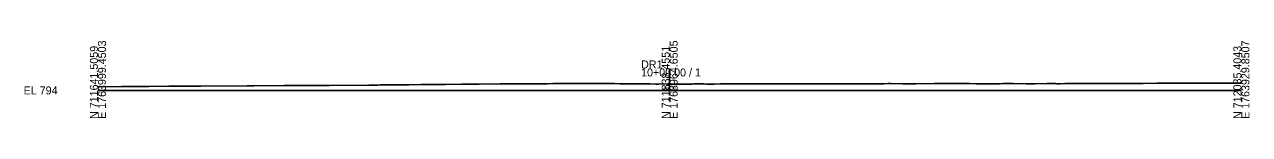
# Model space of a CAD drawing. Extents: x -26 to 403, y -10 to 2023.
# Drawn here: x -25.7 to 402.8, y -9.7 to 17.3 of the extents above; entities that cross this region are included whole.
import ezdxf

# ---------------------------------------------------------------- set-up
doc = ezdxf.new("R2010")
doc.units = 0
for name, color, linetype in [('Exist Cross Section Cell', 7, 'Continuous'), ('Exist XS Center Line Elevation Label', 7, 'Continuous'), ('Exist XS Ground Line', 7, 'Continuous')]:
    doc.layers.add(name, color=color, linetype=linetype)

msp = doc.modelspace()

# ---------------------------------------------------------------- linework, layer by layer
at = {"layer": 'Exist Cross Section Cell'}
for p, q in [((200, 0), (200, 7.69)), ((0, 0), (200, 0)), ((200, 0), (400, 0))]:
    msp.add_line(p, q, dxfattribs=at)
at = {"layer": 'Exist XS Ground Line'}
msp.add_lwpolyline([(0, 1.29), (0.57, 1.3), (8.3, 1.34), (9.9, 1.35), (11.26, 1.36), (12.43, 1.37), (14.28, 1.38), (14.97, 1.38), (16.73, 1.39), (17.82, 1.4), (24.81, 1.45), (26.57, 1.46), (27.67, 1.47), (28.43, 1.48), (31.35, 1.5), (35.98, 1.53), (52.25, 1.62), (53.93, 1.64), (54.48, 1.64), (65.05, 1.69), (66.66, 1.7), (70.69, 1.72), (71.27, 1.72), (77.56, 1.73), (79.66, 1.75), (80.09, 1.75), (80.92, 1.76), (94.82, 1.87), (97.46, 1.88), (97.86, 1.88), (98.71, 1.9), (108.77, 1.99), (112.91, 2.03), (113.98, 2.04), (115.2, 2.05), (116, 2.06), (116.52, 2.06), (119.1, 2.09), (120.82, 2.11), (121.12, 2.11), (121.57, 2.12), (127.19, 2.16), (127.57, 2.16), (128.26, 2.18), (129.22, 2.19), (131.41, 2.18), (131.75, 2.18), (133.34, 2.24), (134.5, 2.26), (136.83, 2.24), (137.58, 2.25), (139.37, 2.24), (140.67, 2.25), (141.91, 2.26), (143.75, 2.25), (144.45, 2.26), (146.99, 2.28), (147.7, 2.29), (149.52, 2.32), (149.92, 2.32), (152.06, 2.33), (153, 2.33), (154.6, 2.33), (156.08, 2.33), (157.14, 2.33), (159.17, 2.39), (159.68, 2.39), (162.25, 2.39), (164.76, 2.39), (165.33, 2.39), (167.3, 2.42), (168.42, 2.41), (169.83, 2.39), (171.5, 2.4), (172.37, 2.4), (174.58, 2.4), (174.91, 2.4), (176.44, 2.41), (177.67, 2.42), (179.99, 2.37), (180.75, 2.37), (182.53, 2.33), (183.84, 2.32), (185.07, 2.31), (186.92, 2.3), (187.61, 2.31), (190.24, 2.28), (190.81, 2.28), (192.68, 2.28), (193.09, 2.28), (195.22, 2.23), (196.17, 2.24), (197.76, 2.25), (199.25, 2.24), (200.3, 2.23), (202.34, 2.21), (202.84, 2.21), (205.42, 2.18), (207.92, 2.24), (208.5, 2.25), (210.45, 2.26), (211.82, 2.25), (212.99, 2.24), (214.67, 2.24), (215.53, 2.23), (217.75, 2.25), (218.07, 2.25), (218.81, 2.27), (219.7, 2.28), (220.03, 2.28), (220.48, 2.28), (227.05, 2.3), (227.39, 2.3), (227.95, 2.29), (229.23, 2.3), (230.09, 2.3), (230.76, 2.3), (231.24, 2.3), (232.93, 2.3), (234.64, 2.32), (235.84, 2.32), (237.01, 2.32), (237.42, 2.32), (241.01, 2.33), (241.43, 2.33), (242.16, 2.33), (243.72, 2.33), (250.46, 2.32), (254.76, 2.3), (256.15, 2.3), (257.13, 2.3), (257.84, 2.3), (258.69, 2.3), (259.92, 2.3), (260.92, 2.3), (261.78, 2.29), (262.66, 2.3), (263.07, 2.3), (270.18, 2.31), (270.53, 2.31), (271.11, 2.32), (272.35, 2.33), (273.26, 2.34), (273.92, 2.34), (274.97, 2.34), (276.46, 2.36), (277.41, 2.36), (281.6, 2.34), (282.04, 2.35), (282.71, 2.35), (283.82, 2.35), (286.05, 2.35), (292.51, 2.36), (296.87, 2.36), (297.41, 2.36), (298.23, 2.37), (299.61, 2.36), (301.01, 2.36), (301.85, 2.36), (302.6, 2.36), (304.39, 2.38), (304.91, 2.38), (307.18, 2.35), (308.43, 2.35), (309.46, 2.35), (310.46, 2.35), (311.22, 2.34), (313.22, 2.34), (314.14, 2.35), (314.54, 2.35), (315.38, 2.35), (316.63, 2.36), (317.08, 2.36), (317.71, 2.36), (319.51, 2.37), (320.21, 2.37), (324.72, 2.34), (325.37, 2.34), (326.28, 2.35), (327.7, 2.35), (332, 2.36), (332.95, 2.37), (334.49, 2.38), (334.93, 2.38), (335.47, 2.34), (336.6, 2.35), (338.2, 2.36), (340.68, 2.38), (345.03, 2.41), (348.4, 2.42), (348.85, 2.41), (349.73, 2.4), (350.56, 2.4), (352.42, 2.4), (355.35, 2.41), (357.46, 2.43), (361.41, 2.45), (362.85, 2.46), (363.22, 2.46), (365.68, 2.47), (370.37, 2.5), (372.49, 2.51), (377.59, 2.5), (378.03, 2.49), (379.96, 2.51), (383.89, 2.53), (388.96, 2.54), (390.7, 2.56), (391.96, 2.55), (393.07, 2.53), (394.56, 2.54), (396.88, 2.54), (397.87, 2.55), (399.69, 2.55), (400, 2.55)], dxfattribs=at)

# ---------------------------------------------------------------- texts
at = {"layer": 'Exist Cross Section Cell'}
for s, p in [('E 1763999.4503', (2.8, -10)), ('E 1763964.6505', (202.8, -10)), ('E 1763929.8507', (402.8, -10)), ('N 711641.5059', (0, -10)), ('N 711838.4551', (200, -10)), ('N 712035.4043', (400, -10))]:
    msp.add_text(s, height=2.8, rotation=90, dxfattribs=at).set_placement(p)
for s, p in [('DR1', (190, 7.69)), ('10+00.00 / 1', (190, 4.89)), ('EL 794', (-26, -1.4))]:
    msp.add_text(s, height=2.8, dxfattribs=at).set_placement(p)
at = {"layer": 'Exist XS Center Line Elevation Label'}
msp.add_text('796.23', height=1, dxfattribs=at).set_placement((197.85, 0.23))

doc.saveas('drawing.dxf')
